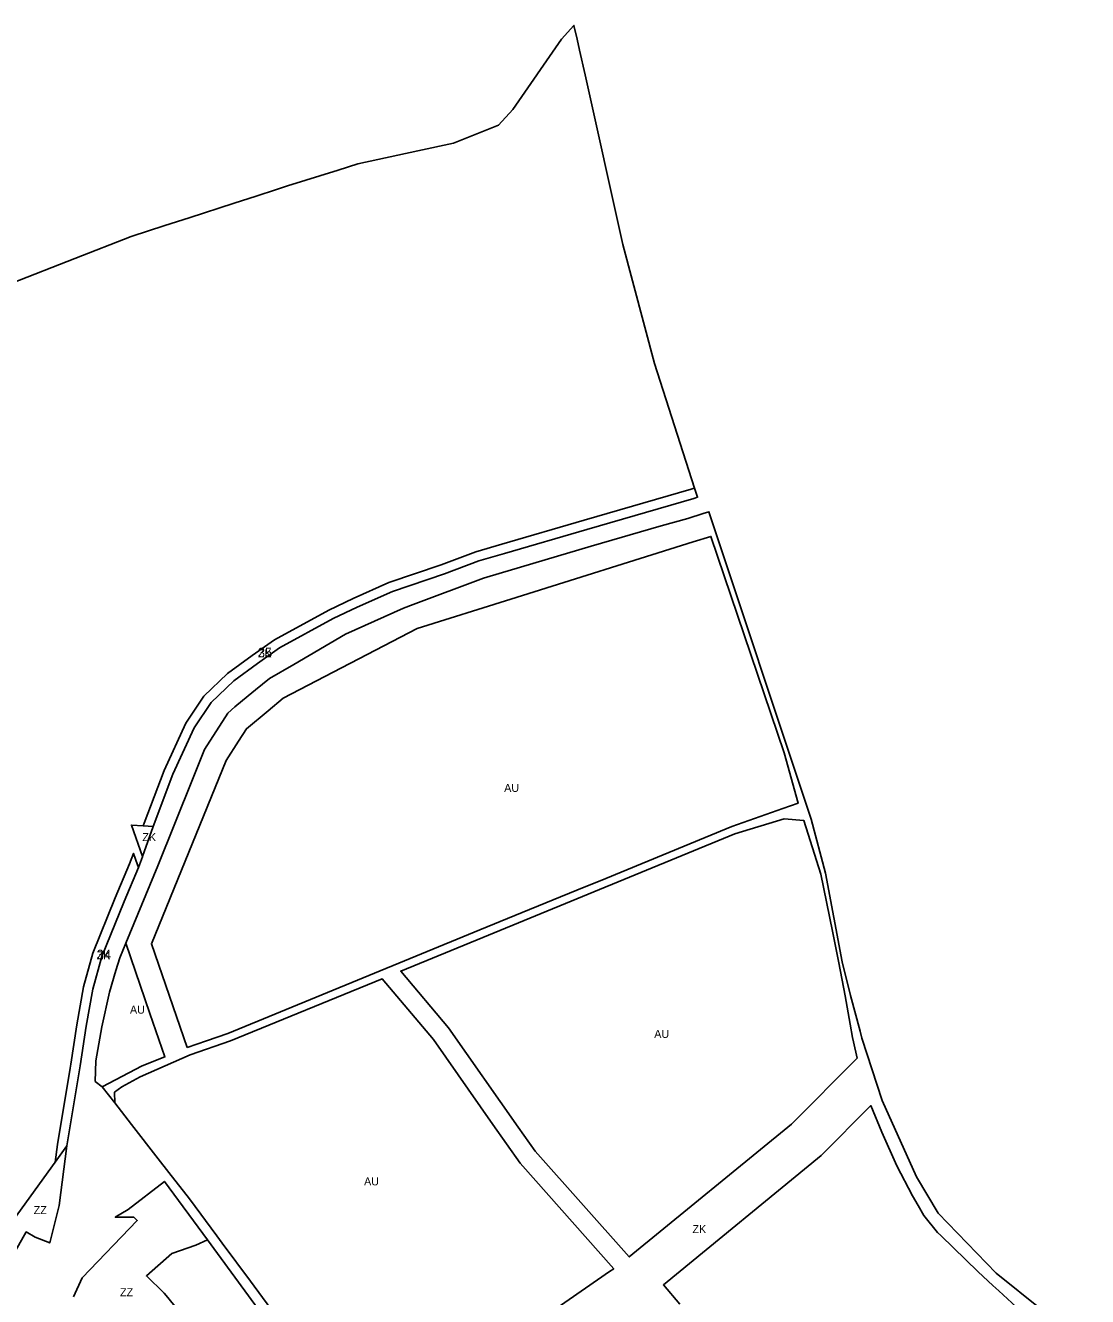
# Model space of a CAD drawing. Extents: x -522079 to -518833, y -1142398 to -1139961.
# Drawn here: x -520390 to -519727, y -1140756 to -1139961 of the extents above; entities that cross this region are included whole.
import ezdxf

# ---------------------------------------------------------------- set-up
doc = ezdxf.new("R2010")
doc.units = 0
for name, color, linetype in [('90670013', 7, 'Continuous'), ('90710013', 7, 'Continuous'), ('90710023', 7, 'Continuous'), ('90750013', 7, 'Continuous'), ('ID_navrh', 7, 'Continuous')]:
    doc.layers.add(name, color=color, linetype=linetype)

msp = doc.modelspace()

# ---------------------------------------------------------------- linework, layer by layer
at = {"layer": '90670013'}
msp.add_lwpolyline([(-520371.84, -1140671.62), (-520364.42, -1140661.36), (-520369.41, -1140698.76), (-520375.15, -1140722.06), (-520384.29, -1140718.48), (-520389.9, -1140715.22), (-520396.68, -1140726.94), (-520400.9, -1140724.3), (-520399.85, -1140722.62), (-520405.96, -1140718.81), (-520371.84, -1140671.63)], close=True, dxfattribs=at)
msp.add_lwpolyline([(-520360.42, -1140755.8), (-520354.98, -1140743.86), (-520320.58, -1140707.95), (-520322.69, -1140705.99), (-520334.3, -1140706.02), (-520326.31, -1140701.14), (-520303.56, -1140683.6), (-520276.72, -1140720.19), (-520284.03, -1140723.41), (-520298.98, -1140728.74), (-520314.83, -1140742.62), (-520303.74, -1140753.44), (-520302.54, -1140754.92), (-520285.25, -1140776.21)], dxfattribs=at)
at = {"layer": '90710013'}
for points in [[(-520083.41, -1140780.15), (-520025.44, -1140739.97), (-520022.9, -1140738.15), (-520081.44, -1140672.17), (-520098.36, -1140648.01), (-520135.55, -1140594.91), (-520167.57, -1140556.99), (-520262.2, -1140595.87), (-520287.56, -1140604.5), (-520318.61, -1140618.22), (-520330.21, -1140624.54), (-520334.77, -1140627.95), (-520334.5, -1140634.63), (-520342.44, -1140624.55), (-520317.54, -1140611.38), (-520303.27, -1140605.8), (-520312.59, -1140578.66), (-520327.66, -1140534.75), (-520307.77, -1140486.46), (-520286.11, -1140432.61), (-520278.46, -1140413.78), (-520263.92, -1140391.15), (-520259.52, -1140387.05), (-520251.21, -1140380.2), (-520246.72, -1140376.59), (-520237.84, -1140369.42), (-520222.7, -1140360.61), (-520190.37, -1140341.83), (-520154.29, -1140325.48), (-520148.17, -1140323.1), (-520104.17, -1140306.68), (-520102.1, -1140306.15), (-520037.05, -1140286.83), (-519993.22, -1140274.03), (-519976.66, -1140269.42), (-519967, -1140266.42), (-519963.47, -1140265.25), (-519901.13, -1140452.27), (-519899.47, -1140457.37), (-519890.68, -1140491.02), (-519880.22, -1140546.4), (-519874.89, -1140567.55), (-519868.98, -1140589.75), (-519867.83, -1140594.09), (-519855.18, -1140633.03), (-519833.7, -1140680.7), (-519820.17, -1140703.4), (-519783.91, -1140740.96), (-519726.89, -1140786.75)], [(-519768.84, -1140764.57), (-519782.42, -1140752.04), (-519786.12, -1140748.61), (-519795.23, -1140740.19), (-519818.61, -1140717.36), (-519820.55, -1140715.47), (-519829.11, -1140704.83), (-519832.73, -1140698.73), (-519836.32, -1140692.64), (-519846.13, -1140673.83), (-519855.49, -1140652.85), (-519862.3, -1140636.3), (-519893.23, -1140667.47), (-519991.87, -1140748.27), (-519981.63, -1140760.4)]]:
    msp.add_lwpolyline(points, dxfattribs=at)
for points in [[(-520289.45, -1140599.87), (-520277.29, -1140595.78), (-520263.96, -1140591.19), (-520201.76, -1140565.63), (-520182.86, -1140557.87), (-520106.55, -1140526.52), (-520084.71, -1140517.54), (-520041.44, -1140499.76), (-520031.39, -1140495.83), (-519949.02, -1140461.79), (-519917.2, -1140450.72), (-519907.62, -1140447.38), (-519916.36, -1140415.97), (-519962.19, -1140280.64), (-519973.33, -1140284.13), (-520087.13, -1140319.85), (-520145.65, -1140338.22), (-520229.31, -1140381.82), (-520238.71, -1140389.58), (-520252.32, -1140400.85), (-520257.35, -1140408.66), (-520265.09, -1140420.72), (-520311.64, -1140535.23)], [(-520310.52, -1140461.93), (-520317.28, -1140480.73), (-520324.15, -1140461.03), (-520316.75, -1140461.52)], [(-520104.66, -1140531.14), (-520155.91, -1140552.2), (-520126.03, -1140587.59), (-520082.56, -1140649.64), (-520072.01, -1140664.71), (-520013.2, -1140730.8), (-519911.88, -1140647.84), (-519870.83, -1140606.54), (-519873.07, -1140596.47), (-519873.69, -1140593.69), (-519875.11, -1140585.42), (-519878.23, -1140567.62), (-519882.2, -1140547.1), (-519886.24, -1140527.38), (-519893.54, -1140491.71), (-519904.17, -1140458.14), (-519916.36, -1140457.2), (-519947.24, -1140466.47)]]:
    msp.add_lwpolyline(points, close=True, dxfattribs=at)
at = {"layer": '90710023'}
for points in [[(-520310.52, -1140461.93), (-520316.75, -1140461.52), (-520316.15, -1140459.86), (-520303.81, -1140426.86), (-520290.26, -1140397.28), (-520278.94, -1140380.49), (-520264.1, -1140366.33), (-520248.84, -1140355.12), (-520234.9, -1140345.26), (-520200.96, -1140326.65), (-520185.56, -1140319.41), (-520163.36, -1140309.5), (-520130.65, -1140298.32), (-520109.13, -1140290.25), (-520092.7, -1140285.53), (-520041.27, -1140270.53), (-519974.44, -1140251.14), (-519972.61, -1140250.6), (-519972.39, -1140250.5), (-519970.54, -1140256.24), (-519972.75, -1140256.9), (-520039.59, -1140276.29), (-520091.03, -1140291.29), (-520107.24, -1140295.95), (-520128.63, -1140303.97), (-520161.16, -1140315.09), (-520183.06, -1140324.86), (-520198.24, -1140332), (-520231.71, -1140350.36), (-520245.33, -1140359.99), (-520260.24, -1140370.94), (-520274.33, -1140384.38), (-520285.01, -1140400.23), (-520298.27, -1140429.16)], [(-520371.84, -1140671.62), (-520370.36, -1140660.47), (-520362.5, -1140612.89), (-520362.06, -1140610.41), (-520358.32, -1140585.75), (-520354.07, -1140562.1), (-520348.31, -1140541.08), (-520334.28, -1140506.54), (-520325.43, -1140485.29), (-520322.93, -1140478.71), (-520320.44, -1140485.82), (-520319.85, -1140487.51), (-520328.73, -1140508.82), (-520342.62, -1140543.01), (-520348.21, -1140563.43), (-520352.4, -1140586.73), (-520356.14, -1140611.39), (-520356.59, -1140613.91), (-520364.42, -1140661.36)]]:
    msp.add_lwpolyline(points, close=True, dxfattribs=at)
at = {"layer": '90750013'}
for points in [[(-520398.93, -1140122.43), (-520359.48, -1140107), (-520324.32, -1140093.25), (-520303.34, -1140086.47), (-520288.09, -1140081.53), (-520260.01, -1140072.45), (-520246.26, -1140068.01), (-520233.47, -1140063.87), (-520226.58, -1140061.71), (-520194.98, -1140051.81), (-520182.69, -1140047.96), (-520145.26, -1140039.86), (-520123.02, -1140035.05), (-520094.95, -1140023.82), (-520085.97, -1140013.91), (-520055.62, -1139970.09), (-520047.76, -1139961.42), (-520045.81, -1139969.91), (-520044.21, -1139976.9), (-520040.68, -1139992.3), (-520017.23, -1140098.3), (-519997.42, -1140172.65), (-519972.39, -1140250.5), (-519972.61, -1140250.6), (-519974.44, -1140251.14), (-520041.27, -1140270.53), (-520092.7, -1140285.53), (-520109.13, -1140290.25), (-520130.65, -1140298.32), (-520163.36, -1140309.5), (-520185.56, -1140319.41), (-520200.96, -1140326.65), (-520234.9, -1140345.26), (-520248.84, -1140355.12), (-520264.1, -1140366.33), (-520278.94, -1140380.49), (-520290.26, -1140397.28), (-520303.81, -1140426.86), (-520316.15, -1140459.86), (-520316.75, -1140461.52), (-520324.15, -1140461.03), (-520317.28, -1140480.73), (-520317.29, -1140480.75), (-520319.85, -1140487.51), (-520320.44, -1140485.82), (-520322.93, -1140478.71), (-520325.43, -1140485.29), (-520334.28, -1140506.54), (-520348.31, -1140541.08), (-520354.07, -1140562.1), (-520358.32, -1140585.75), (-520362.06, -1140610.41), (-520362.5, -1140612.89), (-520370.36, -1140660.47), (-520371.84, -1140671.62), (-520371.84, -1140671.63), (-520405.96, -1140718.81)], [(-520216.26, -1140791.5), (-520249.86, -1140745.99), (-520267.51, -1140722.14), (-520270.86, -1140717.61), (-520287.89, -1140694.59), (-520300.9, -1140678.05), (-520307.57, -1140669.43), (-520324.2, -1140648.06), (-520334.5, -1140634.63), (-520334.77, -1140627.95), (-520330.21, -1140624.54), (-520318.61, -1140618.22), (-520287.56, -1140604.5), (-520262.2, -1140595.87), (-520167.57, -1140556.99), (-520135.55, -1140594.91), (-520098.36, -1140648.01), (-520081.44, -1140672.17), (-520022.9, -1140738.15), (-520025.44, -1140739.97), (-520083.41, -1140780.15)], [(-519981.63, -1140760.4), (-519991.87, -1140748.27), (-519893.23, -1140667.47), (-519862.3, -1140636.3), (-519855.49, -1140652.85), (-519846.13, -1140673.83), (-519836.32, -1140692.64), (-519832.73, -1140698.73), (-519829.11, -1140704.83), (-519820.55, -1140715.47), (-519818.61, -1140717.36), (-519795.23, -1140740.19), (-519786.12, -1140748.61), (-519782.42, -1140752.04), (-519768.84, -1140764.57)]]:
    msp.add_lwpolyline(points, dxfattribs=at)
for points in [[(-520289.45, -1140599.87), (-520311.64, -1140535.23), (-520265.09, -1140420.72), (-520257.35, -1140408.66), (-520252.32, -1140400.85), (-520238.71, -1140389.58), (-520229.31, -1140381.82), (-520145.65, -1140338.22), (-520087.13, -1140319.85), (-519973.33, -1140284.13), (-519962.19, -1140280.64), (-519916.36, -1140415.97), (-519907.62, -1140447.38), (-519917.2, -1140450.72), (-519949.02, -1140461.79), (-520031.39, -1140495.83), (-520041.44, -1140499.76), (-520084.71, -1140517.54), (-520106.55, -1140526.52), (-520182.86, -1140557.87), (-520201.76, -1140565.63), (-520263.96, -1140591.19), (-520277.29, -1140595.78)], [(-520104.66, -1140531.14), (-519947.24, -1140466.47), (-519916.36, -1140457.2), (-519904.17, -1140458.14), (-519893.54, -1140491.71), (-519886.24, -1140527.38), (-519882.2, -1140547.1), (-519878.23, -1140567.62), (-519875.11, -1140585.42), (-519873.69, -1140593.69), (-519873.07, -1140596.47), (-519870.83, -1140606.54), (-519911.88, -1140647.84), (-520013.2, -1140730.8), (-520072.01, -1140664.71), (-520082.56, -1140649.64), (-520126.03, -1140587.59), (-520155.91, -1140552.2)], [(-520346.89, -1140621.24), (-520346.39, -1140608.35), (-520342.68, -1140587.14), (-520337.95, -1140565.45), (-520333.94, -1140551.84), (-520331.42, -1140543.88), (-520327.66, -1140534.75), (-520312.59, -1140578.66), (-520303.27, -1140605.8), (-520317.54, -1140611.38), (-520342.44, -1140624.55)], [(-520306.3, -1140797.86), (-520298.77, -1140787.91), (-520285.25, -1140776.21), (-520302.54, -1140754.92), (-520303.74, -1140753.44), (-520314.83, -1140742.62), (-520298.98, -1140728.74), (-520284.03, -1140723.41), (-520276.72, -1140720.19), (-520215.27, -1140803.99), (-520216.9, -1140807.42), (-520249.32, -1140803.75)]]:
    msp.add_lwpolyline(points, close=True, dxfattribs=at)

# ---------------------------------------------------------------- texts
at = {"layer": '90670013'}
for p in [(-520385.19, -1140704.023), (-520331.285, -1140755.379)]:
    msp.add_text('ZZ', height=5, rotation=360, dxfattribs=at).set_placement(p)
at = {"layer": '90710013'}
for p in [(-520317.335, -1140471.027), (-519973.696, -1140715.915)]:
    msp.add_text('ZK', height=5, rotation=0, dxfattribs=at).set_placement(p)
at = {"layer": '90710023'}
for p in [(-520245.161, -1140356.215), (-520345.845, -1140544.901)]:
    msp.add_text('ZK', height=5, rotation=0, dxfattribs=at).set_placement(p)
at = {"layer": '90750013'}
for rotation, p in [(360, (-520091.317, -1140440.255)), (0, (-520325.08, -1140578.818)), (360, (-519997.58, -1140594)), (360, (-520178.835, -1140686.113))]:
    msp.add_text('AU', height=5, rotation=rotation, dxfattribs=at).set_placement(p)
at = {"layer": 'ID_navrh'}
for s, p in [('35', (-520245.161, -1140356.215)), ('34', (-520345.845, -1140544.901))]:
    msp.add_text(s, height=6, rotation=0, dxfattribs=at).set_placement(p)

doc.saveas('drawing.dxf')
